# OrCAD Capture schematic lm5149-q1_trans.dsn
size D; title: LM5149-Q1: 80-V Automotive Synchronous Buck DC/DC; rev: 1.0; note: Datasheet: SNVSBN7     EVM: SNVU773; note: Controller with Ultra-Low IQ and Integrated Active EMI Filter
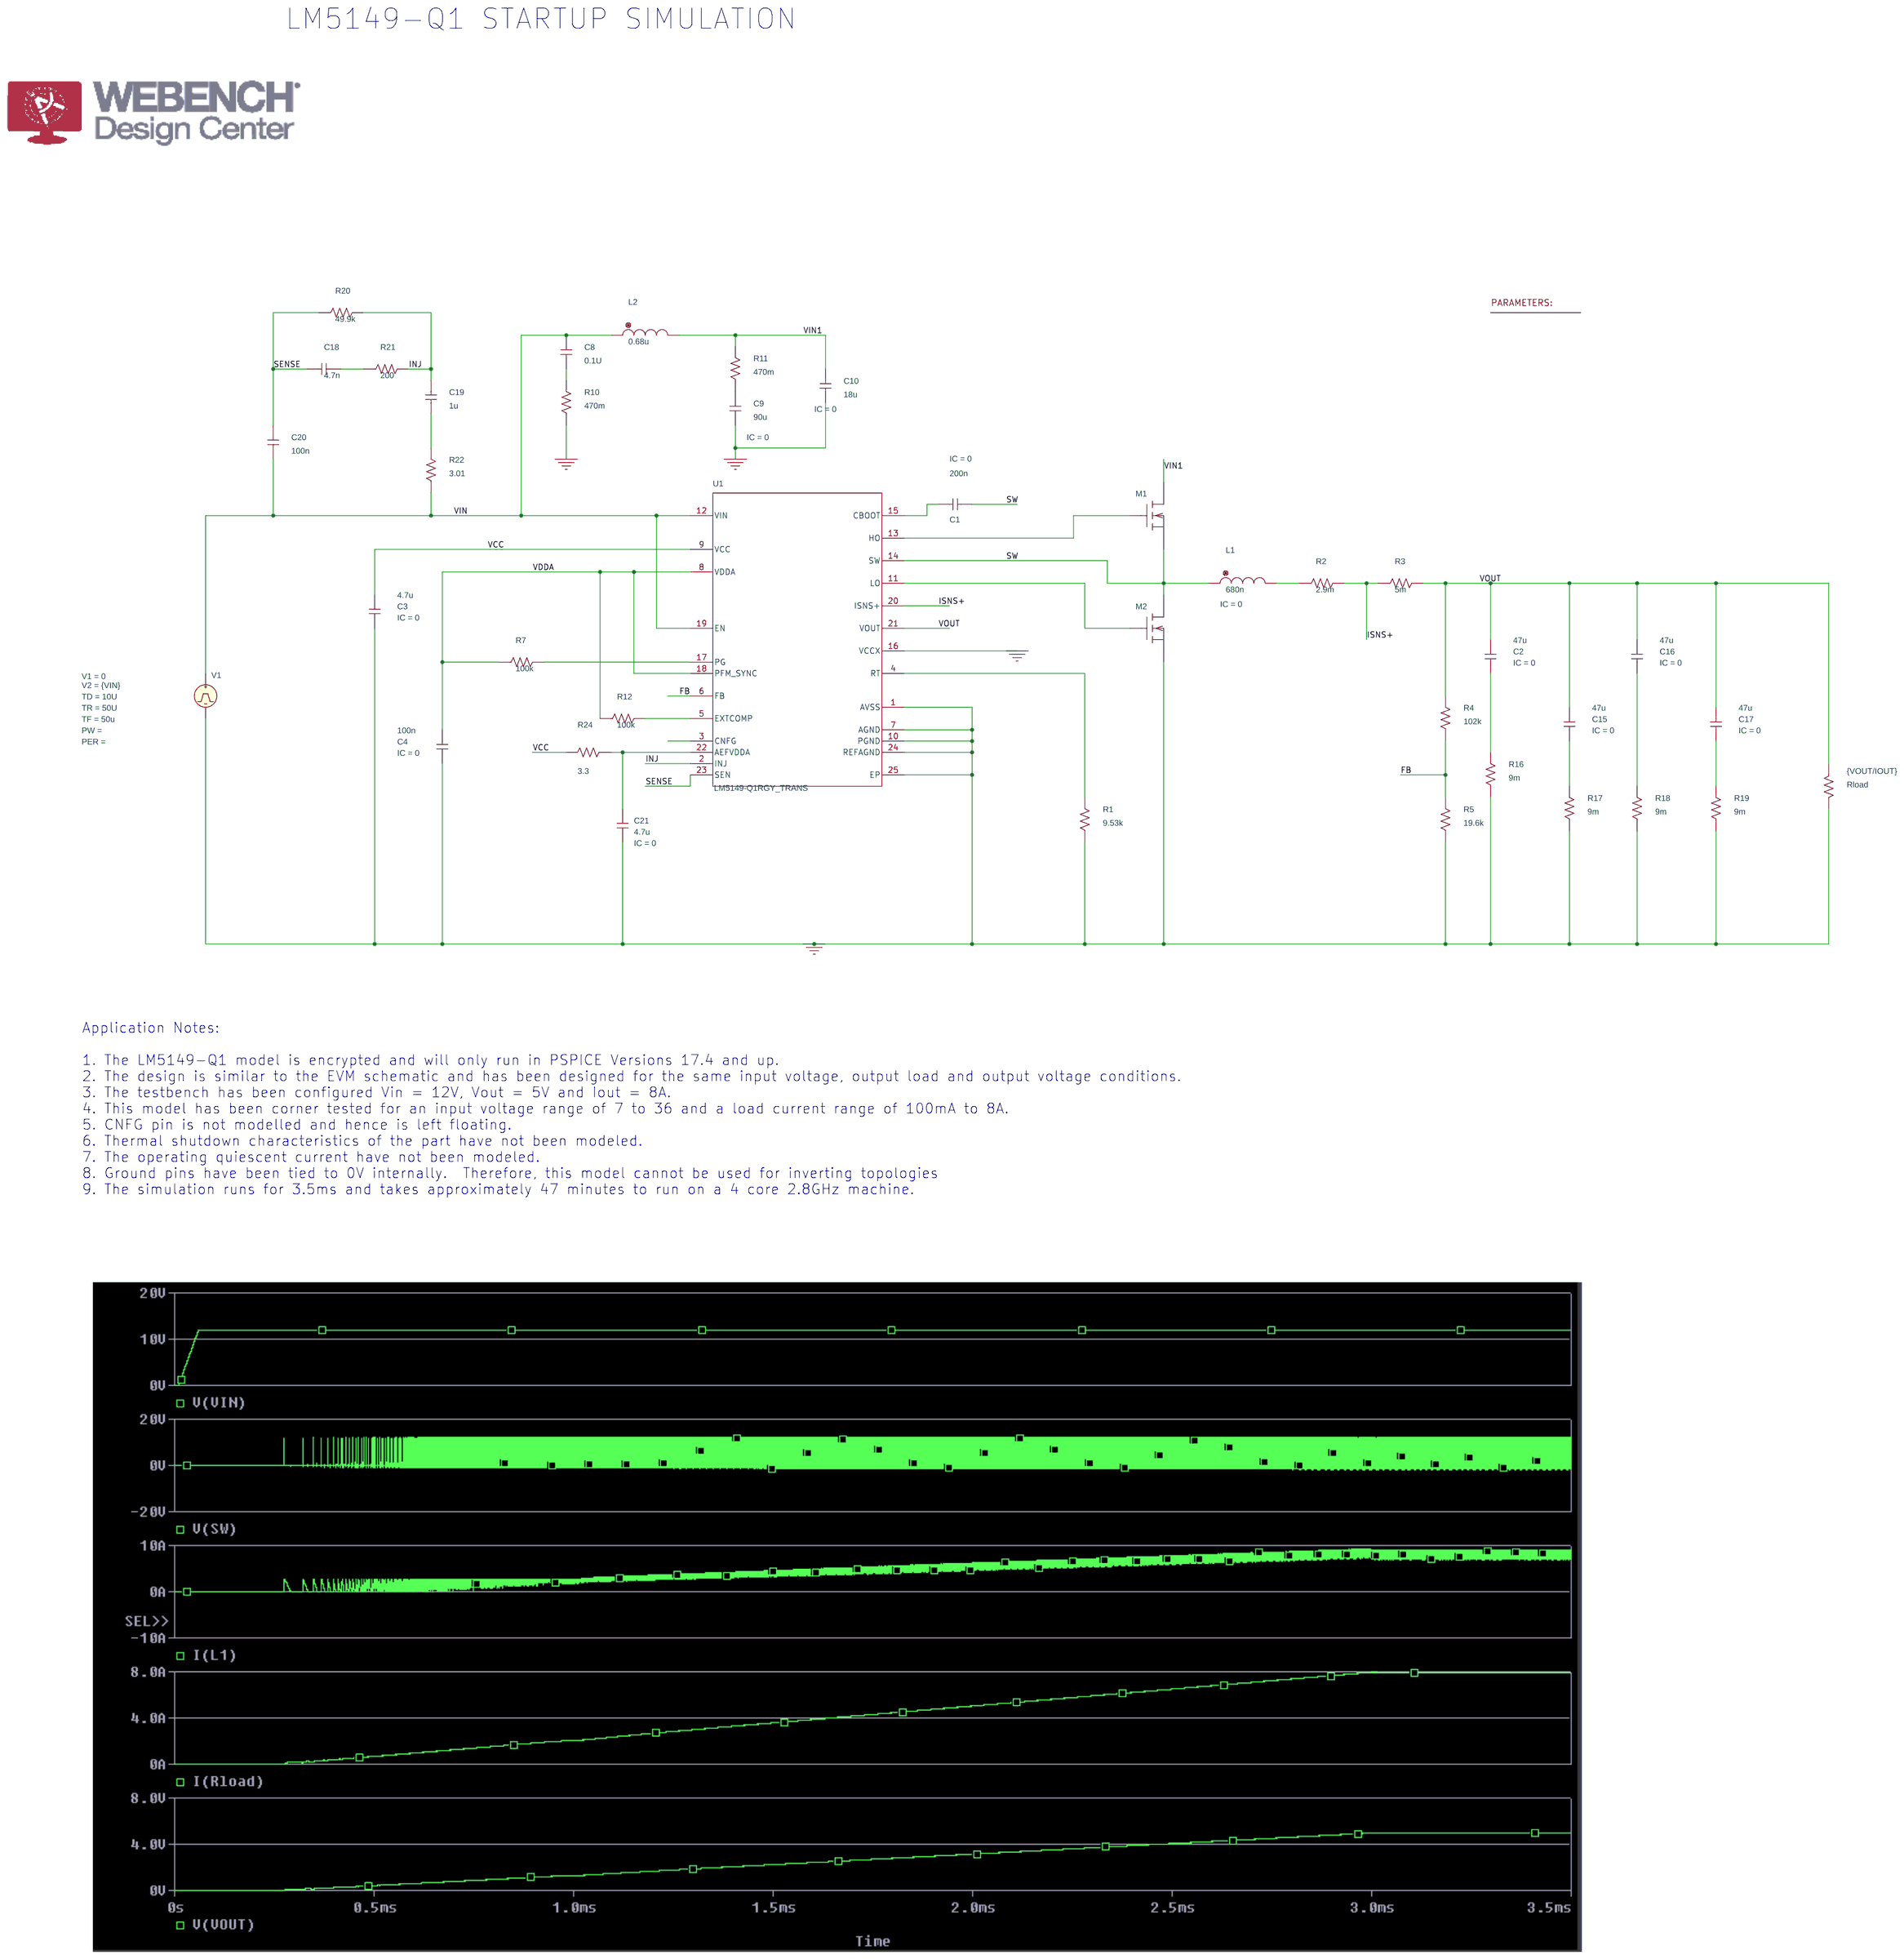
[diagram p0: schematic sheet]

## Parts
1  PARAM
C1  200n  [cap196]
C2  47u  [cap196]
C3  4.7u  [cap196]
C4  100n  [cap196]
C8  0.1U  [cap196]
C9  90u  [cap196]
C10  18u  [cap196]
C15  47u  [cap196]
C16  47u  [cap196]
C17  47u  [cap196]
C18  4.7n  [cap196]
C19  1u  [cap196]
C20  100n  [cap196]
C21  4.7u  [cap196]
L1  680n  [DISC350x175LS200x100034]
L2  0.68u  [DISC350x175LS200x100034]
M1  power_Mbreakn
M2  power_Mbreakn
R1  9.53k  [AXRC05]
R2  2.9m  [AXRC05]
R3  5m  [AXRC05]
R4  102k  [AXRC05]
R5  19.6k  [AXRC05]
R7  100k  [AXRC05]
R10  470m  [AXRC05]
R11  470m  [AXRC05]
R12  100k  [AXRC05]
R16  9m  [AXRC05]
R17  9m  [AXRC05]
R18  9m  [AXRC05]
R19  9m  [AXRC05]
R20  49.9k  [AXRC05]
R21  200  [AXRC05]
R22  3.01  [AXRC05]
R24  3.3  [AXRC05]
Rload  {VOUT/IOUT}  [AXRC05]
U1  LM5149-Q1RGY_TRANS  [RGY0024E-MFG]
V1  VPULSE

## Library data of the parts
1 = PARAM: IOUT: 8; Steady_State: 0; VIN: 12; VOUT: 5
C1-C4 C9 C10 C15-C17 C21 = C: IC: 0
C8 C18-C20 = C
L1 = L: IC: 0
L2 = L
M1 M2 = power_Mbreakn
R1-R5 R7 R10-R12 R16-R22 R24 Rload = R
U1 = LM5149-Q1RGY_TRANS: STEADY_STATE: 0
V1 = VPULSE: TD: 10U; TF: 50u; TR: 50U; V1: 0; V2: {VIN}

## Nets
VCC: C3.1 R24.2 U1.9(VCC)
VDDA: C4.1 R7.1 R12.1 U1.8(VDDA) U1.18(PFM_SYNC)
VIN: C8.2 C20.1 L2.1 R22.1 U1.12(VIN) U1.19(EN) V1.1(+)
VIN1: C10.2 L2.2 M1.2(d) R11.2
0: C3.2 C4.2 C9.1 C10.1 C21.1 M2.0(s) R1.1 R5.1 R10.1 R16.1 R17.1 R18.1 R19.1 Rload.2 U1.1(AVSS) U1.7(AGND) U1.10(PGND) U1.16(VCCX) U1.24(REFAGND) U1.25(EP) V1.2(-)
FB: R4.1 R5.2 U1.6(FB)
INJ: C19.2 R20.2 R21.2 U1.2(INJ)
ISNS+: R2.2 R3.1 U1.20(ISNS+)
SENSE: C18.1 C20.2 R20.1 U1.23(SEN)
SW: C1.2 L1.1 M1.0(s) M2.2(d) U1.14(SW)
VOUT: C2.1 C15.1 C16.1 C17.1 R3.2 R4.2 Rload.1 U1.21(VOUT)
N16771012: C18.2 R21.1
N16771030: C8.1 R10.2
N16771114: C19.1 R22.2
N16771310: C1.1 U1.15(CBOOT)
N16771366: M1.1(g) U1.13(HO)
N16771504: M2.1(g) U1.11(LO)
N16771526: L1.2 R2.1
N16771744: R7.2 U1.17(PG)
N16771756: R1.2 U1.4(RT)
N16771764: C2.2 R16.2
N16771770: C16.2 R18.2
N16771886: R12.2 U1.5(EXTCOMP)
N16771990: C15.2 R17.2
N16771996: C17.2 R19.2
N16772008: C21.2 R24.1 U1.22(AEFVDDA)
N16776396: C9.2 R11.1

Not connected (* = marked no-connect by the designer): U1 3(CNFG)

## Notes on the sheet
- LM5149-Q1 STARTUP SIMULATION
- Application Notes:
  1. The LM5149-Q1 model is encrypted and will only run in PSPICE Versions 17.4 and up.
  2. The design is similar to the EVM schematic and has been designed for the same input voltage, output load and output voltage conditions.
  3. The testbench has been configured Vin = 12V, Vout = 5V and Iout = 8A.
  4. This model has been corner tested for an input voltage range of 7 to 36 and a load current range of 100mA to 8A.
  5. CNFG pin is not modelled and hence is left floating.
  6. Thermal shutdown characteristics of the part have not been modeled.
  7. The operating quiescent current have not been modeled.
  8. Ground pins have been tied to 0V internally.  Therefore, this model cannot be used for inverting topologies
  9. The simulation runs for 3.5ms and takes approximately 47 minutes to run on a 4 core 2.8GHz machine.
